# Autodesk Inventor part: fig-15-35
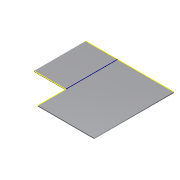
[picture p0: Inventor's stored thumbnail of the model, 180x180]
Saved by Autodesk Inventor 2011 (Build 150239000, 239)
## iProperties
Created: 2005-03
Part Number: fig-15-35
Document SubType Name: Sheet Metal
Designer: CADCIM
Manufacturer: Standard
Standards Organization: Custom
Density: 1 g/cm^3
Sheet Metal Rule: Default
Author: CADCIM
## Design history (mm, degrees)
node "Face1"
  sketch "Sketch1"
    geometry: L1 (31.393, 35.714)-(-19.875, 35.714); L2 (-19.875, 35.714)-(-19.875, 5.625); L3 (-19.875, 5.625)-(-1.5, 5.625); L4 (-1.5, 5.625)-(-1.5, -10.705); L5 (-1.5, -10.705)-(31.393, -10.705); L6 (31.393, -10.705)-(31.393, 35.714)
    constraints: 12 end point, 4 parallel, 1 horizontal, 1 perpendicular
sketch "Sketch3"
  geometry: L1 (18.375, -30.089)-(18.375, 0); L2 (18.375, -46.42)-(18.375, -30.089) reference; L3 (18.375, -30.089)-(0, -30.089) reference; L4 (0, 0)-(51.268, 0) reference
  constraints: 3 point on line, 2 end point, 1 vertical
body "Solid1"
face "Plate1" dims "Thickness" = 0.5
other parameters: "BendRadius" = 0.5 (= Thickness), "BendReliefWidth" = 0.5 (= Thickness), "BendReliefDepth" = 0.25 (= 0.5 x Thickness), "CornerReliefSize" = 2 (= 4 x Thickness), "SeamGap" = 0.01, "MinimumRemnant" = 1 (= 2 x Thickness), "TransitionRadius" = 0.5 (= BendRadius), "d0" = 0.5 (= BendRadius), "JacobiRadiusSize" = 0.5 (= Thickness), "GapSize" = 0.5 (= Thickness)
